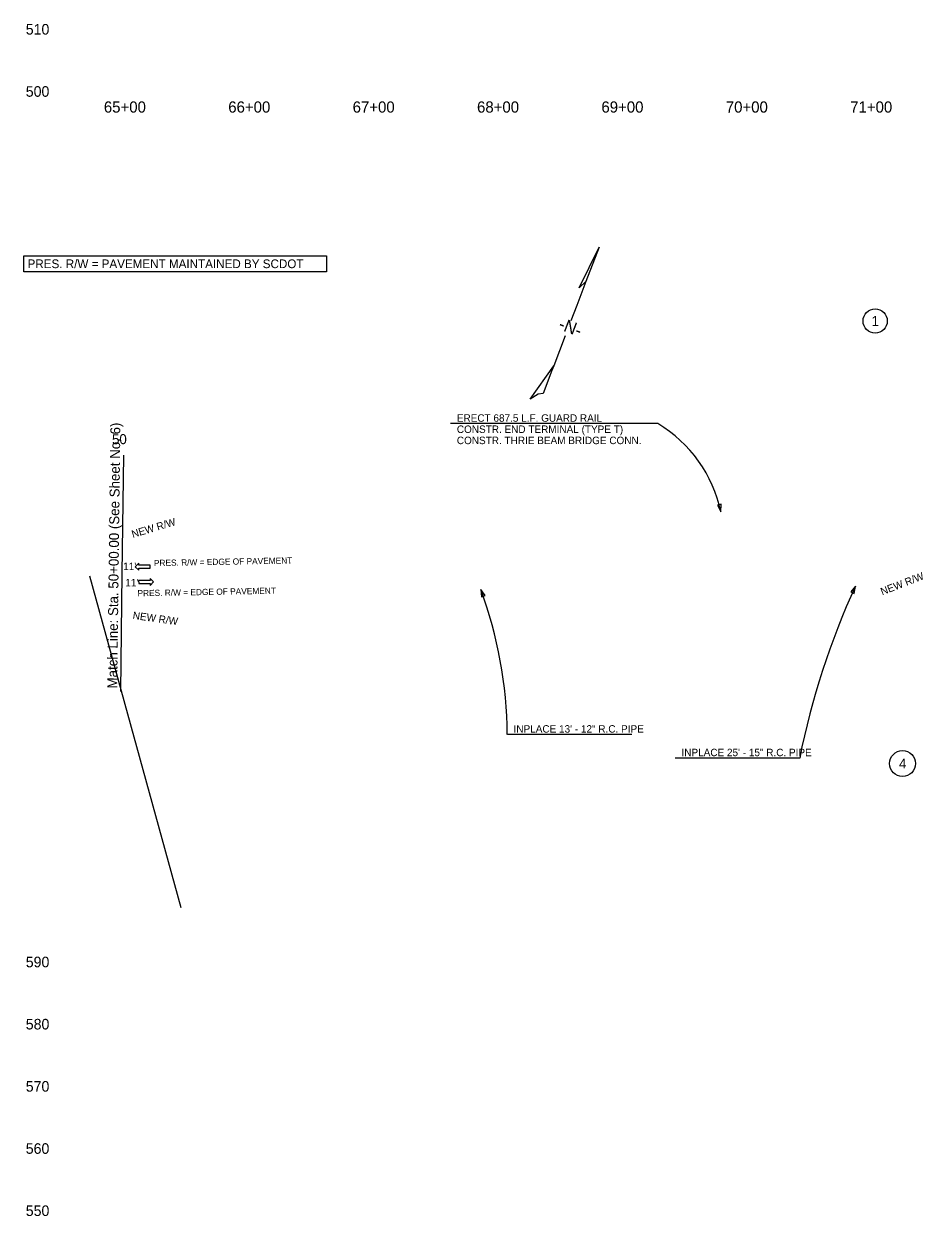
# Model space of a CAD drawing. Extents: x 1964377 to 1966966, y 1116414 to 1123213.
# Drawn here: x 1965292 to 1966010, y 1117827 to 1118785 of the extents above; entities that cross this region are included whole.
import ezdxf

# ---------------------------------------------------------------- set-up
doc = ezdxf.new("R2010")
doc.units = 0
for name, color, linetype in [('RD_DDB_Profile_Elev', 7, 'Continuous'), ('RD_DDB_StaTX', 7, 'Continuous'), ('RD_EX_DV_Prop', 7, 'Continuous'), ('RD_EX_DV_TX_Prop', 7, 'Continuous'), ('RD_EX_Misc', 7, 'Continuous'), ('RD_EX_RW_TX', 7, 'Continuous'), ('RD_HC_TX_Sta50', 7, 'Continuous'), ('RD_PD_Final_LnLine', 7, 'Continuous'), ('RD_PD_Final_TX', 7, 'Continuous'), ('RD_PD_RW_TX', 7, 'Continuous'), ('RD_SHT_MatchLine', 7, 'Continuous'), ('RD_TX_Drainage', 7, 'Continuous'), ('RD_TX_Misc1', 7, 'Continuous')]:
    doc.layers.add(name, color=color, linetype=linetype)

msp = doc.modelspace()

# ---------------------------------------------------------------- linework, layer by layer
at = {"layer": 'RD_EX_DV_Prop'}
msp.add_line((1965344.94, 1118341.51), (1965418.61, 1118074.8), dxfattribs=at)
at = {"layer": 'RD_EX_DV_TX_Prop'}
for centre, radius in [((1965976.69, 1118546.47), 9.72), ((1965998.71, 1118190.63), 10.4)]:
    msp.add_circle(centre, radius, dxfattribs=at)
at = {"layer": 'RD_EX_Misc'}
for p, q in [((1965738.65, 1118573.02), (1965754.74, 1118605.83)), ((1965754.74, 1118605.83), (1965744.17, 1118578.15)), ((1965744.17, 1118578.15), (1965736.84, 1118558.95)), ((1965744.17, 1118578.15), (1965738.65, 1118573.02)), ((1965736.84, 1118558.95), (1965732.16, 1118546.72)), ((1965727.5, 1118534.5), (1965718.26, 1118510.3)), ((1965699.23, 1118483.6), (1965718.26, 1118510.3)), ((1965716.86, 1118506.64), (1965709.78, 1118488.1)), ((1965718.26, 1118510.3), (1965716.86, 1118506.64))]:
    msp.add_line(p, q, dxfattribs=at)
msp.add_lwpolyline([(1965709.78, 1118488.1), (1965705.78, 1118487.55), (1965699.23, 1118483.6)], dxfattribs=at)
at = {"layer": 'RD_EX_RW_TX'}
msp.add_lwpolyline([(1965292.29, 1118598.99), (1965535.65, 1118598.99), (1965535.65, 1118585.99), (1965292.29, 1118585.99)], close=True, dxfattribs=at)
at = {"layer": 'RD_PD_Final_LnLine'}
for points in [[(1965393.84, 1118347.81), (1965393.81, 1118350.21), (1965384.64, 1118350.12), (1965384.62, 1118351.75), (1965381.82, 1118348.89), (1965384.68, 1118346.09), (1965384.66, 1118347.72)], [(1965384.59, 1118337.81), (1965384.62, 1118335.41), (1965393.79, 1118335.5), (1965393.81, 1118333.87), (1965396.6, 1118336.73), (1965393.75, 1118339.53), (1965393.76, 1118337.9)]]:
    msp.add_lwpolyline(points, close=True, dxfattribs=at)
at = {"layer": 'RD_SHT_MatchLine'}
msp.add_lwpolyline([(1965370.31, 1118248.55), (1965371.45, 1118343.55), (1965372.58, 1118438.54)], dxfattribs=at)
at = {"layer": 'RD_TX_Drainage'}
for p, q in [((1965781.02, 1118213.98), (1965680.99, 1118213.98)), ((1965916.02, 1118195.03), (1965815.99, 1118195.03))]:
    msp.add_line(p, q, dxfattribs=at)
for points in [[(1965959.84, 1118327.3), (1965960.85, 1118333.22), (1965957.02, 1118328.6)], [(1965663.09, 1118325.65), (1965659.63, 1118330.56), (1965660.17, 1118324.58)]]:
    msp.add_lwpolyline(points, close=True, dxfattribs=at)
for centre, radius, start, end in [((1966520.54, 1118075.28), 616.26, 155.2567, 168.79491), ((1965332.41, 1118210.38), 348.59, 0.5931, 20.16728)]:
    msp.add_arc(centre, radius, start, end, dxfattribs=at)
at = {"layer": 'RD_TX_Misc1'}
msp.add_line((1965802, 1118463.96), (1965635.39, 1118463.96), dxfattribs=at)
msp.add_lwpolyline([(1965849.93, 1118398.47), (1965852.65, 1118393.12), (1965852.96, 1118399.12)], close=True, dxfattribs=at)
msp.add_arc((1965746.05, 1118370.43), 108.99, 12.01968, 59.11486, dxfattribs=at)

# ---------------------------------------------------------------- texts
at = {"layer": 'RD_DDB_Profile_Elev'}
for s, p in [('510', (1965293.84, 1118776.8)), ('500', (1965293.84, 1118726.8)), ('590', (1965293.84, 1118026.8)), ('580', (1965293.84, 1117976.8)), ('570', (1965293.84, 1117926.8)), ('560', (1965293.84, 1117876.8)), ('550', (1965293.84, 1117826.8))]:
    msp.add_text(s, height=8.5, dxfattribs=at).set_placement(p)
at = {"layer": 'RD_DDB_StaTX'}
for s, p in [('65+00', (1965356.62, 1118714.05)), ('66+00', (1965456.62, 1118714.05)), ('67+00', (1965556.62, 1118714.05)), ('68+00', (1965656.62, 1118714.05)), ('69+00', (1965756.62, 1118714.05)), ('70+00', (1965856.62, 1118714.05)), ('71+00', (1965956.62, 1118714.05))]:
    msp.add_text(s, height=9, dxfattribs=at).set_placement(p)
at = {"layer": 'RD_EX_DV_TX_Prop'}
for s, p in [('1', (1965973.77, 1118542.48)), ('4', (1965995.87, 1118186.64))]:
    msp.add_text(s, height=8, dxfattribs=at).set_placement(p)
at = {"layer": 'RD_EX_Misc'}
msp.add_text('-N-', height=10, rotation=339.09664, dxfattribs=at).set_placement((1965721.35, 1118540.21))
at = {"layer": 'RD_EX_RW_TX'}
msp.add_text('PRES. R/W = PAVEMENT MAINTAINED BY SCDOT', height=7, dxfattribs=at).set_placement((1965295.29, 1118588.99))
for p in [(1965396.9, 1118349.35), (1965383.71, 1118325.07)]:
    msp.add_text('PRES. R/W = EDGE OF PAVEMENT', height=5, rotation=1.09247, dxfattribs=at).set_placement(p)
at = {"layer": 'RD_HC_TX_Sta50'}
msp.add_text('50', height=8, rotation=1.09248, dxfattribs=at).set_placement((1965363.23, 1118447.31))
at = {"layer": 'RD_PD_Final_TX'}
for p in [(1965372.16, 1118346.27), (1965373.82, 1118333.14)]:
    msp.add_text("11'", height=6, dxfattribs=at).set_placement(p)
at = {"layer": 'RD_PD_RW_TX'}
for rotation, p in [(16.52349, (1965379.89, 1118372.04)), (21.11702, (1965982.38, 1118325.87)), (351.99112, (1965379.55, 1118306.97))]:
    msp.add_text('NEW R/W', height=6, rotation=rotation, dxfattribs=at).set_placement(p)
at = {"layer": 'RD_SHT_MatchLine'}
msp.add_text('Match Line: Sta. 50+00.00 (See Sheet No. 6)', height=8, rotation=89.31507, dxfattribs=at).set_placement((1965367.34, 1118250.94))
at = {"layer": 'RD_TX_Drainage'}
for s, p in [('INPLACE 13\' - 12" R.C. PIPE', (1965685.99, 1118215.48)), ('INPLACE 25\' - 15" R.C. PIPE', (1965820.99, 1118196.53))]:
    msp.add_text(s, height=6, dxfattribs=at).set_placement(p)
at = {"layer": 'RD_TX_Misc1'}
for s, p in [('ERECT 687.5 L.F. GUARD RAIL', (1965640.39, 1118465.46)), ('CONSTR. END TERMINAL (TYPE T)', (1965640.39, 1118456.46)), ('CONSTR. THRIE BEAM BRIDGE CONN.', (1965640.39, 1118447.46))]:
    msp.add_text(s, height=6, dxfattribs=at).set_placement(p)

doc.saveas('drawing.dxf')
